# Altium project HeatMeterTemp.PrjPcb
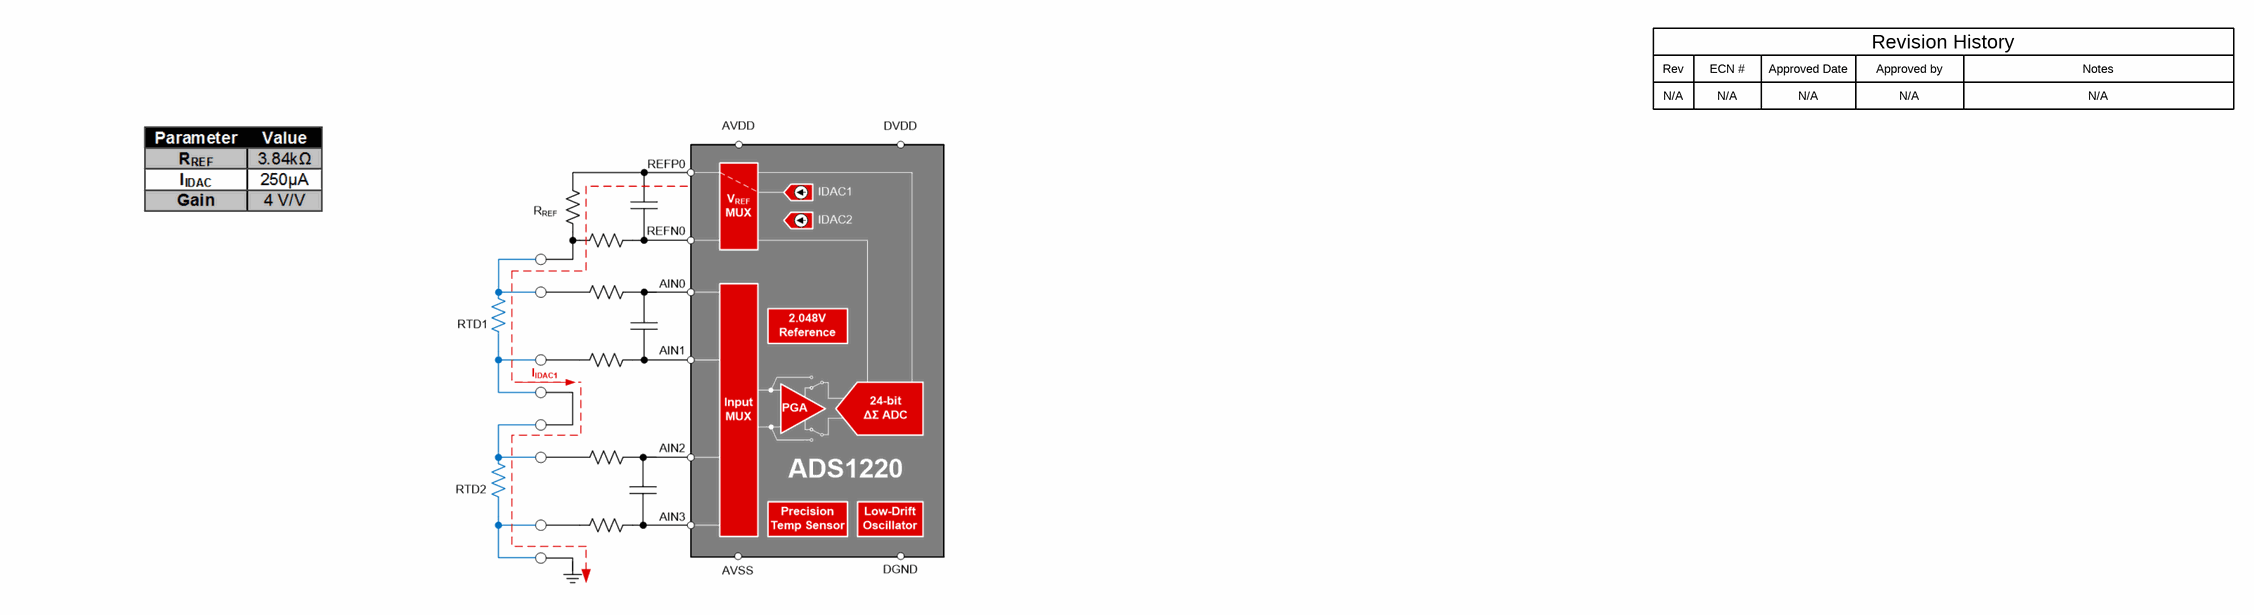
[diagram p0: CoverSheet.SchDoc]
CopyrightYear: 2017; EVM_orderable: shippable; PCB_Layouta0797195: Who did the Layout?; PCB_Rev: E1; PRJ_Customer: Public Release; PRJ_Engineer: MGS; PRJ_Number: TIDA-01526; PRJ_Title: Heat Meter dual 2-/4-wire RTD measurement; SCH_Rev: E1; TechSupport: http://www.ti.com/support; TID: TIDA-01526
3 sheets, 61 parts. Net scope: flat (ports and power ports of the same name join across sheets).
Board file: HeatMeterTemp.PcbDoc
Sheets:
  CoverSheet.SchDoc
  RTD_ADS122U04.SchDoc
  HeatMeterTemp_Hardware.SchDoc

## Sheet CoverSheet.SchDoc
size 431 x 279 mm; Date: Not shown in title block; ApprovedBy: Not shown in title block; CheckedBy: Not shown in title block; Author: Not shown in title block; CompanyName: Not shown in title block; Engineer: Not shown in title block; Organization: Not shown in title block; Address1: Not shown in title block; Address2: Not shown in title block; Address3: Not shown in title block; Address4: Not shown in title block; DocumentNumber: 1; Revision: Use project parameter SCH_Rev; SheetNumber: 1; SheetTotal: 3; PageSetup: Record=PageOptions¦CenterHorizontal=True¦CenterVertical=True¦PrintScale=1.00¦XCorrection=1.00¦YCorrection=1.00¦PrintKind=0¦BorderSize=5000000¦LeftOffset=0¦BottomOffset=0¦Orientation=2¦PaperLength=1000¦PaperWidth=1000¦Scale=100¦PaperSource=15¦PrintQuality=600¦MediaType=1¦DitherType=10¦PaperKind=Letter¦PrintScaleMode=1

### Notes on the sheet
- Rev
- N/A
- ECN #
- Approved Date
- Approved by
- Revision History
- Notes

## Sheet RTD_ADS122U04.SchDoc
size 431 x 279 mm; Date: Not shown in title block; ApprovedBy: Not shown in title block; CheckedBy: Not shown in title block; Author: Not shown in title block; CompanyName: Not shown in title block; Engineer: Not shown in title block; Organization: Not shown in title block; Address1: Not shown in title block; Address2: Not shown in title block; Address3: Not shown in title block; Address4: Not shown in title block; DocumentNumber: 1; Revision: Use project parameter SCH_Rev; SheetNumber: 2; SheetTotal: 3; PageSetup: Record=PageOptions¦CenterHorizontal=True¦CenterVertical=True¦PrintScale=1.00¦XCorrection=1.00¦YCorrection=1.00¦PrintKind=0¦BorderSize=5000000¦LeftOffset=0¦BottomOffset=0¦Orientation=2¦PaperLength=1000¦PaperWidth=1000¦Scale=100¦PaperSource=15¦PrintQuality=600¦MediaType=1¦DitherType=10¦PaperKind=Letter¦PrintScaleMode=1
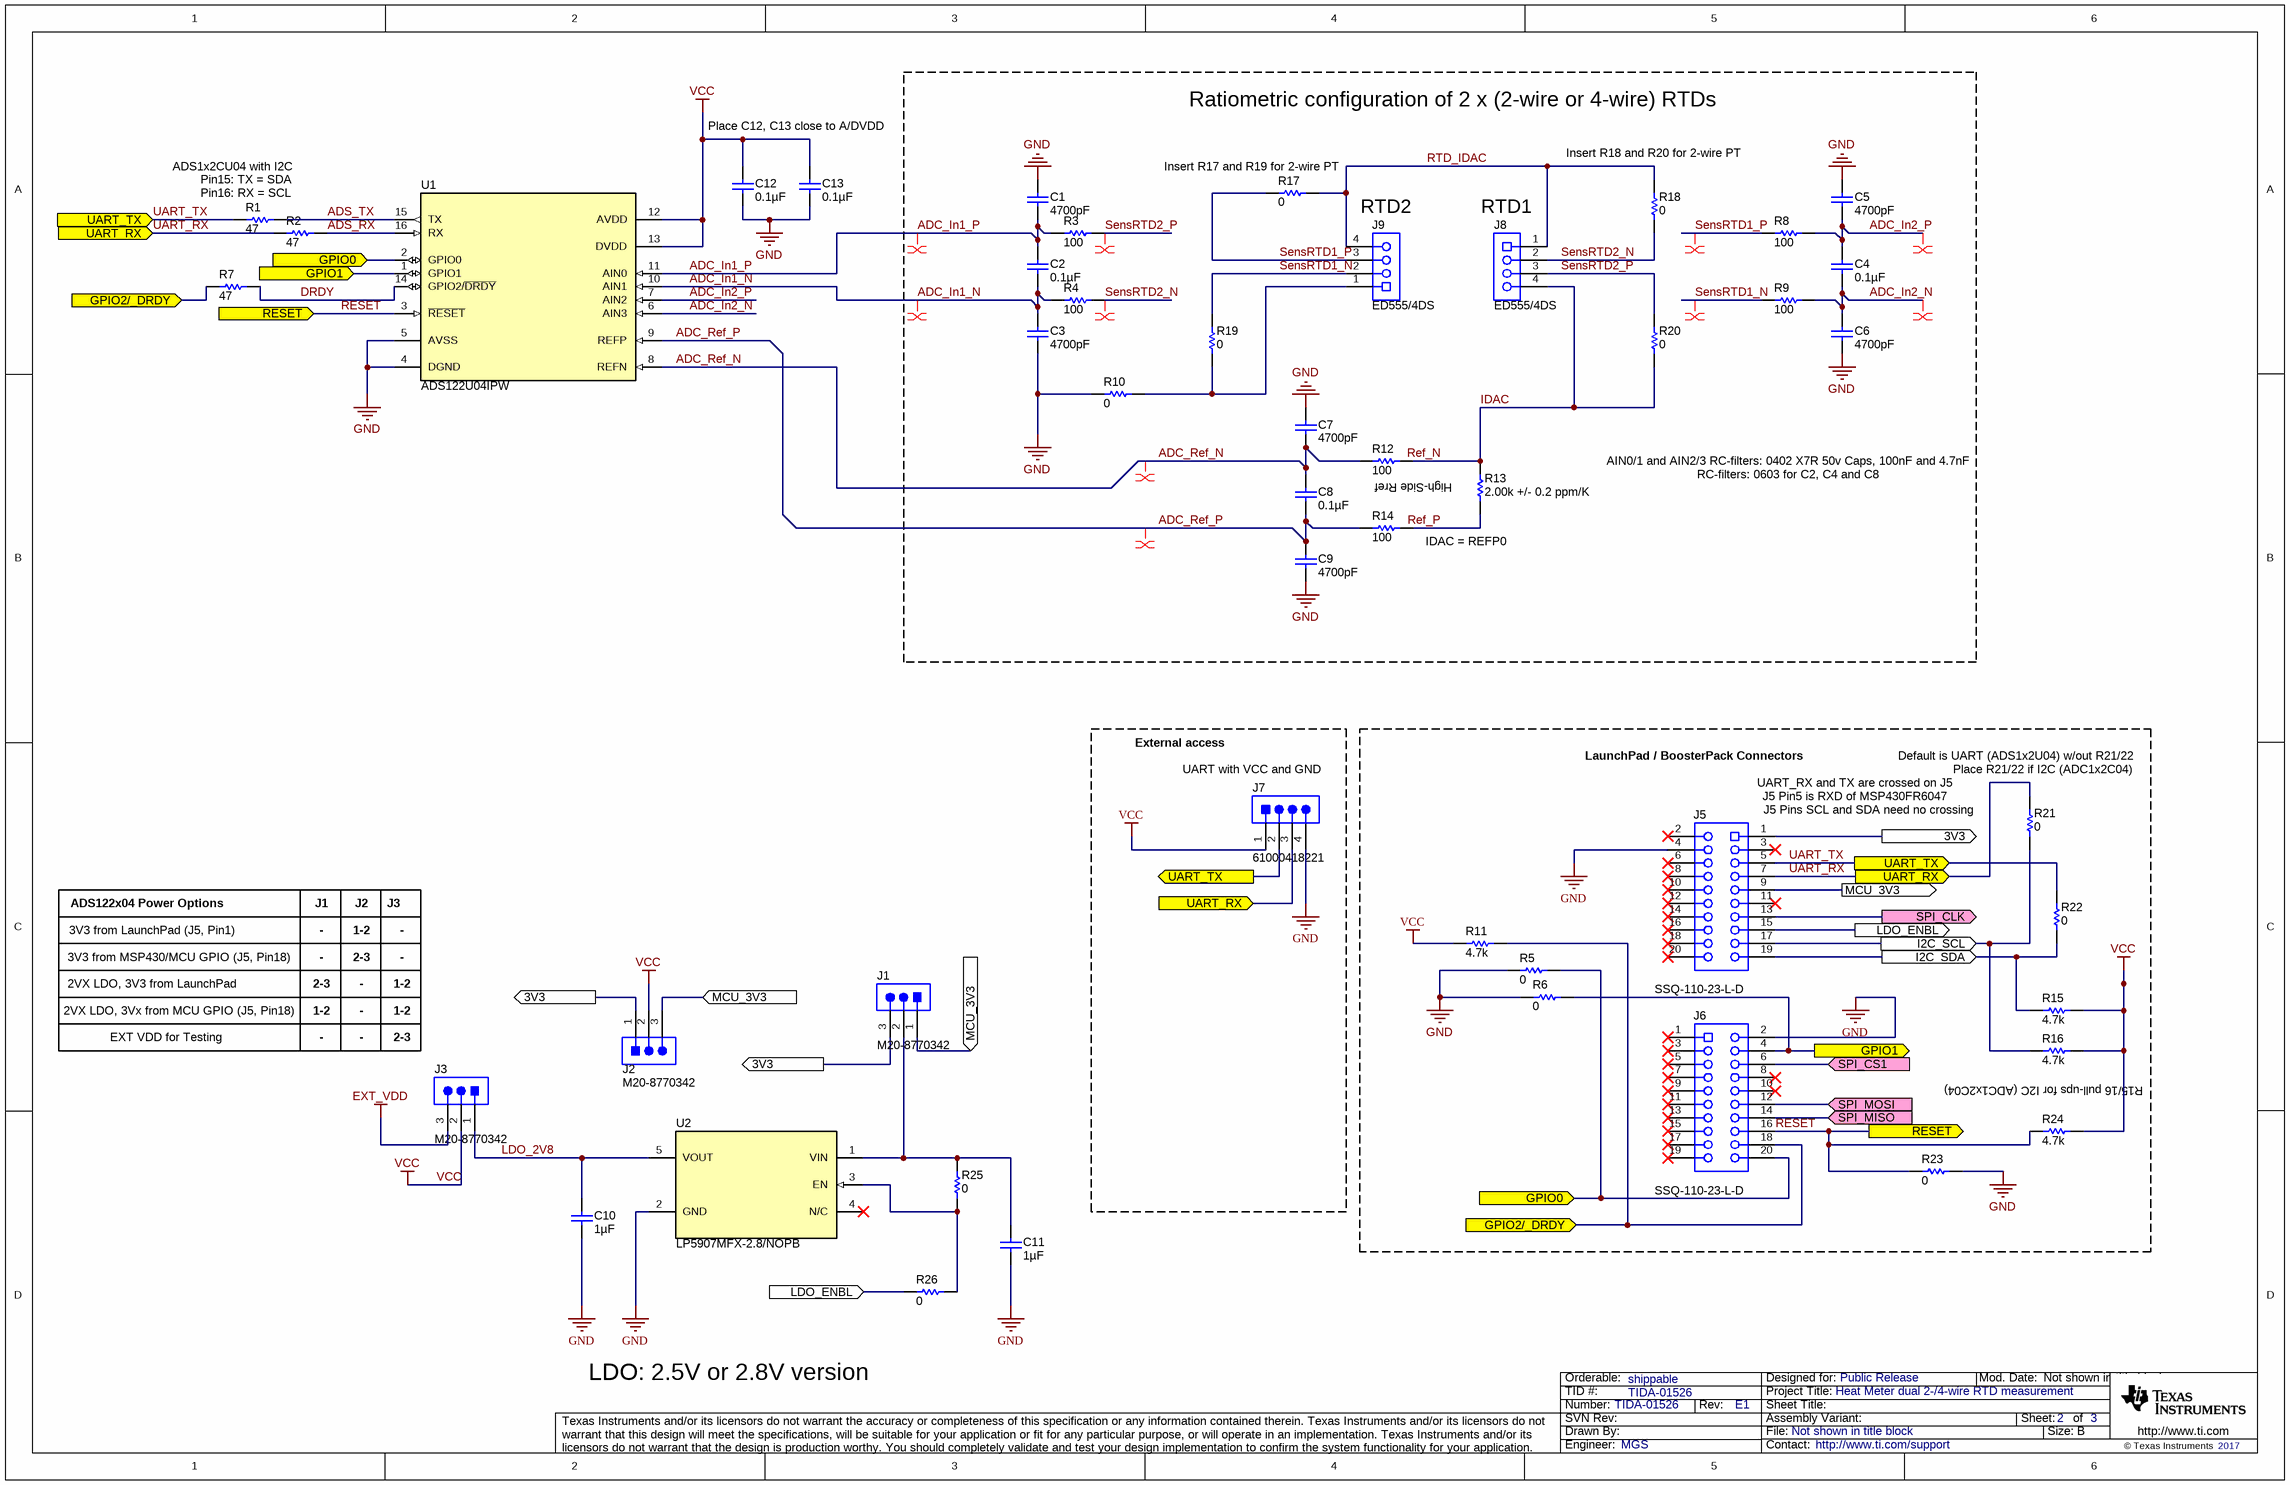
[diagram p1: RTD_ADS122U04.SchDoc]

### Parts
C1  ValueDisplayed: 4700pF  [0402L]  (hidden comment: GCM155R71H472KA37D)
C2  ValueDisplayed: 0.1µF  [0603L]  (hidden comment: GCM188R71H104KA57D)
C3  ValueDisplayed: 4700pF  [0402L]  (hidden comment: GCM155R71H472KA37D)
C4  ValueDisplayed: 0.1µF  [0603L]  (hidden comment: GCM188R71H104KA57D)
C5  ValueDisplayed: 4700pF  [0402L]  (hidden comment: GCM155R71H472KA37D)
C6  ValueDisplayed: 4700pF  [0402L]  (hidden comment: GCM155R71H472KA37D)
C7  ValueDisplayed: 4700pF  [0402L]  (hidden comment: GCM155R71H472KA37D)
C8  ValueDisplayed: 0.1µF  [0603L]  (hidden comment: GCM188R71H104KA57D)
C9  ValueDisplayed: 4700pF  [0402L]  (hidden comment: GCM155R71H472KA37D)
C10  ValueDisplayed: 1µF  [0603L]  (hidden comment: 885012206026)
C11  ValueDisplayed: 1µF  [0603L]  (hidden comment: 885012206026)
C12  ValueDisplayed: 0.1µF  [0402L]  (hidden comment: GRM155R71C104JA88D)
C13  ValueDisplayed: 0.1µF  [0402L]  (hidden comment: GRM155R71C104JA88D)
J1  M20-8770342  [Harwin_M20-87703]
J2  M20-8770342  [Harwin_M20-87703]
J3  M20-8770342  [Harwin_M20-87703]
J5  SSW-110-23-F-D  [CONN_SSW-110-23-F-D]  (value not drawn)
J6  SSW-110-23-F-D  [CONN_SSW-110-23-F-D]  (value not drawn)
J7  61000418221  [Wurth_61000418221]
J8  ED555/4DS  [TERM_BLK_ED555-4DS]
J9  ED555/4DS  [TERM_BLK_ED555-4DS]
R1  ValueDisplayed: 47  [0402L]  (hidden comment: CRCW040247R0JNED)
R2  ValueDisplayed: 47  [0402L]  (hidden comment: CRCW040247R0JNED)
R3  ValueDisplayed: 100  [0402L]  (hidden comment: CRCW0402100RFKED)
R4  ValueDisplayed: 100  [0402L]  (hidden comment: CRCW0402100RFKED)
R5  ValueDisplayed: 0  [0402L]  (hidden comment: CRCW04020000Z0ED)
R6  ValueDisplayed: 0  [0402L]  (hidden comment: CRCW04020000Z0ED)
R7  ValueDisplayed: 47  [0402L]  (hidden comment: CRCW040247R0JNED)
R8  ValueDisplayed: 100  [0402L]  (hidden comment: CRCW0402100RFKED)
R9  ValueDisplayed: 100  [0402L]  (hidden comment: CRCW0402100RFKED)
R10  ValueDisplayed: 0  [0402L]  (hidden comment: CRCW04020000Z0ED)
R11  ValueDisplayed: 4.7k  [0402L]  (hidden comment: CRCW04024K70JNED)
R12  ValueDisplayed: 100  [0402L]  (hidden comment: CRCW0402100RFKED)
R13  ValueDisplayed: 2.00k +/- 0.2 ppm/K  [VSMP_0603]  (hidden comment: Y16362K00000F9R)
R14  ValueDisplayed: 100  [0402L]  (hidden comment: CRCW0402100RFKED)
R15  ValueDisplayed: 4.7k  [0402L]  (hidden comment: CRCW04024K70JNED)
R16  ValueDisplayed: 4.7k  [0402L]  (hidden comment: CRCW04024K70JNED)
R17  ValueDisplayed: 0  [0402L]  (hidden comment: CRCW04020000Z0ED)
R18  ValueDisplayed: 0  [0402L]  (hidden comment: CRCW04020000Z0ED)
R19  ValueDisplayed: 0  [0402L]  (hidden comment: CRCW04020000Z0ED)
R20  ValueDisplayed: 0  [0402L]  (hidden comment: CRCW04020000Z0ED)
R21  ValueDisplayed: 0  [0402L]  (hidden comment: CRCW04020000Z0ED)
R22  ValueDisplayed: 0  [0402L]  (hidden comment: CRCW04020000Z0ED)
R23  ValueDisplayed: 0  [0402L]  (hidden comment: CRCW04020000Z0ED)
R24  ValueDisplayed: 4.7k  [0402L]  (hidden comment: CRCW04024K70JNED)
R25  ValueDisplayed: 0  [0402L]  (hidden comment: CRCW04020000Z0ED)
R26  ValueDisplayed: 0  [0402L]  (hidden comment: CRCW04020000Z0ED)
U1  ADS122U04IPW  [PW0016A_N]
U2  LP5907MFX-2.8/NOPB  [DBV0005A_N]

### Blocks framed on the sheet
Ratiometric configuration of 2 x (2-wire or 4-wire) RTDs: C1-C9 J8 J9 R3 R4 R8-R10 R12-R14 R17-R20

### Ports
3V3, GPIO0, GPIO1, GPIO2/_DRDY, I2C_SCL, I2C_SDA, LDO_ENBL, MCU_3V3, RESET, SPI_CLK, SPI_CS1, SPI_MISO, SPI_MOSI, UART_RX, UART_TX

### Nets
EXT_VDD: J3.3
GND: C1.1 C3.2 C5.1 C6.2 C7.1 C9.2 C10.2 C11.2 C12.1 C13.1 J5.4 J6.2 J7.4 R5.1 R6.1 R10.1 R23.2 U1.4(DGND) U1.5(AVSS) U2.2(GND)
VCC: C12.2 C13.2 J2.2 J3.2 J7.1 R11.1 R15.2 R16.2 R24.2 U1.12(AVDD) U1.13(DVDD)
3V3: J1.3 J2.1 J5.1 ; port 3V3
ADC_In1_N: C2.2 C3.1 R4.1 U1.10(AIN1)
ADC_In1_P: C1.2 C2.1 R3.1 U1.11(AIN0)
ADC_In2_N: C4.2 C6.1 R9.2 U1.6(AIN3)
ADC_In2_P: C4.1 C5.2 R8.2 U1.7(AIN2)
ADC_Ref_N: C7.2 C8.1 R12.1 U1.8(REFN)
ADC_Ref_P: C8.2 C9.1 R14.1 U1.9(REFP)
ADS_RX: R2.2 U1.16(RX)
ADS_TX: R1.2 U1.15(TX)
DRDY: R7.2 U1.14(GPIO2/~{DRDY})
GPIO0: J6.20 R5.2 U1.2(GPIO0) ; port GPIO0
GPIO1: J6.4 R6.2 U1.1(GPIO1) ; port GPIO1
GPIO2/_DRDY: J6.18 R7.1 R11.2 ; port GPIO2/_DRDY
I2C_SCL: J5.17 R16.1 R21.1 ; port I2C_SCL
I2C_SDA: J5.19 R15.1 R22.2 ; port I2C_SDA
IDAC: J8.4 R12.2 R13.2 R20.1
LDO_2V8: C10.1 J3.1 U2.5(VOUT)
LDO_ENBL: J5.15 R26.2 ; port LDO_ENBL
MCU_3V3: J1.1 J2.3 J5.9 ; port MCU_3V3
RESET: J6.16 R23.1 R24.1 U1.3(~{RESET}) ; port RESET
RTD_IDAC: J8.1 J9.4 R17.2 R18.2
SensRTD1_N: J9.2 R9.1 R19.2
SensRTD1_P: J9.3 R8.1 R17.1
SensRTD2_N: J8.2 R4.2 R18.1
SensRTD2_P: J8.3 R3.2 R20.2
SPI_CLK: J5.13 ; port SPI_CLK
SPI_CS1: J6.6 ; port SPI_CS1
SPI_MISO: J6.14 ; port SPI_MISO
SPI_MOSI: J6.12 ; port SPI_MOSI
UART_RX: J5.7 J7.3 R2.1 R21.2 ; port UART_RX
UART_TX: J5.5 J7.2 R1.1 R22.1 ; port UART_TX
NetC11_1: C11.1 J1.2 R25.1 U2.1(VIN)
NetJ9_1: J9.1 R10.2 R19.1
NetR13_1: R13.1 R14.2
NetR25_2: R25.2 R26.1 U2.3(EN)

Not connected (* = marked no-connect by the designer): J5 2* 3* 6* 8* 10* 11* 12* 14* 16* 18* 20*; J6 1* 3* 5* 7* 8* 9* 10* 11* 13* 15* 17* 19*; U2 4(N/C)*

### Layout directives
differential pair: ADC_In1_N, ADC_In1_P, ADC_In2_N, ADC_In2_P, ADC_Ref_N, ADC_Ref_P, SensRTD1_N, SensRTD1_P, SensRTD2_N, SensRTD2_P

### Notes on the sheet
- ADS1x2CU04 with I2C
- Place C12, C13 close to A/DVDD
- (near R17) Insert R17 and R19 for 2-wire PT
- (near R18) Insert R18 and R20 for 2-wire PT
- Pin15: TX = SDA
- Pin16: RX = SCL
- (near J9) RTD2
- (near J8) RTD1
- High-Side Rref
- AIN0/1 and AIN2/3 RC-filters: 0402 X7R 50v Caps, 100nF and 4.7nF
- RC-filters: 0603 for C2, C4 and C8
- IDAC = REFP0
- External access
- (near J7) UART with VCC and GND
- LaunchPad / BoosterPack Connectors
- (near R21) Default is UART (ADS1x2U04) w/out R21/22
- (near R21) Place R21/22 if I2C (ADC1x2C04)
- (near J5) UART_RX and TX are crossed on J5
- (near J5) J5 Pin5 is RXD of MSP430FR6047
- (near J5) J5 Pins SCL and SDA need no crossing
- ADS122x04 Power Options
- J1
- J2
- J3
- 3V3 from LaunchPad (J5, Pin1)
- 3V3 from MSP430/MCU GPIO (J5, Pin18)
- -
- 2-3
- 1-2
- 2VX LDO, 3V3 from LaunchPad
- EXT VDD for Testing
- 2VX LDO, 3Vx from MCU GPIO (J5, Pin18)
- (near J5) SSQ-110-23-L-D
- R15/16 pull-ups for I2C (ADC1x2C04)
- (near J6) SSQ-110-23-L-D
- LDO: 2.5V or 2.8V version
- Labels drawn without touching a wire or pin: Ref_N, Ref_P

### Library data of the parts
C1 C3 C5-C7 C9 = GCM155R71H472KA37D: CAP, CERM, 4700 pF, 50 V,+/- 10%, X7R, AEC-Q200 Grade 1, 0402; Manufacturer: MuRata; Polarized: N; CompType: Capacitor; Value: 4700pF; U/M: EA; Cap_F: 0.0000000047; Tolerance_%: 10; VDC_V: 50; Value2: 50V; TaMin_C: -55; TaMax_C: 125; Cap_Case: 0402; AEC Category: Q200; AEC Qualified: Y; AEC Grade: 1; SizeArea_mm2: 0.5; SizeAreaWB_mm2: 3; SizeZ_mm: 0.6
C2 C4 C8 = GCM188R71H104KA57D: CAP, CERM, 0.1 µF, 50 V,+/- 10%, X7R, 0603; Manufacturer: MuRata; Polarized: N; CompType: Capacitor; Value: 0.1uF; U/M: EA; Cap_F: 0.0000001; Tolerance_%: 10; ESR_ohm: 0.02; Value1: 0.02 ohm; VDC_V: 50; Value2: 50V; IRMS_A: 1.84; TaMin_C: -55; TaMax_C: 125; Cap_Case: 0603; AEC Category: Q200; SizeArea_mm2: 1.28; SizeAreaWB_mm2: 4.68; SizeX_mm: 1.6; SizeY_mm: 0.8; SizeZ_mm: 1; Green_Lifecycle: Active; Green_REACh: Passed
C10 C11 = 885012206026: CAP, CERM, 1 µF, 10 V,+/- 10%, X7R, 0603; Manufacturer: Wurth Elektronik; Polarized: N; CompType: Capacitor; Value: 1uF; U/M: EA; Cap_F: 0.000001; Tolerance_%: 10; Value2: 10V; TaMin_C: -55; TaMax_C: 125; Cap_Case: 0603; SizeArea_mm2: 1.28; SizeAreaWB_mm2: 4.68; SizeX_mm: 1.6; SizeY_mm: 0.8; SizeZ_mm: 1; AEC Category: Q200
C12 C13 = GRM155R71C104JA88D: CAP, CERM, 0.1 µF, 16 V,+/- 5%, X7R, 0402; Manufacturer: MuRata; Polarized: N; CompType: Capacitor; Value: 0.1uF; U/M: EA; Cap_F: 0.0000001; Tolerance_%: 5; VDC_V: 16; Value2: 16V; TaMin_C: -55; TaMax_C: 125; Cap_Case: 0402; AEC Category: Q200; SizeArea_mm2: 0.5; SizeAreaWB_mm2: 3; SizeX_mm: 1; SizeZ_mm: 0.6; Green_Lifecycle: Active; Green_REACh: Passed
J1-J3 = M20-8770342: Header, 2.54mm, 3x1, Gold, SMT; Manufacturer: Harwin; SymbolCreator: a0799628; Pitch_mm: 2.54; Gender: Male; Shrouded: N; Row_Count: 1; Current_A: 3; Cert_UL: Y; Green_Lifecycle: Active; Green_REACh: Passed
J5 J6 = SSW-110-23-F-D: Connector, Receptacle, 100mil, 10x2, Gold plated, TH; Manufacturer: Samtec; SymbolCreator: a0412235; U/M: EA
J7 = 61000418221: Header, 2.54mm, 4x1, Gold, SMT; Manufacturer: Wurth Elektronik; SymbolCreator: a0412235; Pitch_mm: 2.54; Gender: Male; Shrouded: N; Row_Count: 1
J8 J9 = ED555/4DS: Terminal Block, 3.5mm Pitch, 4x1, TH; Manufacturer: On-Shore Technology; SymbolCreator: a0411947; Pitch_mm: 3.5; Gender: Female; Shrouded: N; Row_Count: 1; ContactFinish: Brass; Current_A: 6; Voltage_V: 150; Cert_CULUS: Y; Green_Lifecycle: Not Set; Green_REACh: Incomplete
R1 R2 R7 = CRCW040247R0JNED: RES, 47, 5%, 0.063 W, 0402; Manufacturer: Vishay-Dale; CompType: Resistor; Value: 47; Value_Code: 47R0; Tolerance_%: 5; Power_W: 0.063; Value2: 0.063W; VDC_V: 50; TempCo: 200 ppm/C; EIA_Code: E24; U/M: EA; AEC Category: Q200; SizeArea_mm2: 0.5; SizeX_mm: 1; SizeZ_mm: 0.6; Green_Lifecycle: Active; Green_REACh: Passed
R3 R4 R8 R9 R12 R14 = CRCW0402100RFKED: RES, 100, 1%, 0.063 W, 0402; Manufacturer: Vishay-Dale; CompType: Resistor; Value: 100; Value_Code: 100R; Tolerance_%: 1; Power_W: 0.063; Value2: 0.063W; VDC_V: 50; TempCo: 100 ppm/C; EIA_Code: E96; U/M: EA; AEC Category: Q200
R5 R6 R10 R17-R23 R25 R26 = CRCW04020000Z0ED: RES, 0, 5%, 0.063 W, 0402; Manufacturer: Vishay-Dale; CompType: Resistor; Value: 0; Value_Code: 0000; Tolerance_%: 5; Power_W: 0.063; Value2: 0.063W; VDC_V: 50; TempCo: 200 ppm/C; EIA_Code: E24; U/M: EA; AEC Category: Q200; SizeArea_mm2: 0.5; SizeX_mm: 1; SizeZ_mm: 0.6; Green_Lifecycle: Active; Green_REACh: Passed
R11 R15 R16 R24 = CRCW04024K70JNED: RES, 4.7 k, 5%, 0.063 W, 0402; Manufacturer: Vishay-Dale; CompType: Resistor; Value: 4.7k; Res_ohm: 4700; Value_Code: 4k70; Tolerance_%: 5; Power_W: 0.063; Value2: 0.063W; VDC_V: 50; TempCo: 200 ppm/C; EIA_Code: E24; U/M: EA; AEC Category: Q200; SizeArea_mm2: 0.5; SizeX_mm: 1; SizeZ_mm: 0.6; Green_Lifecycle: Active; Green_REACh: Passed
R13 = Y16362K00000F9R: RES, 2.00 k, 1%, 0.1 W, 0603, +/- 0.2 ppm/K; Manufacturer: Vishay Foil Resistors; CompType: Resistor; Value: 2.00k; Res_ohm: 2000; Value_Code: 2k00; Tolerance_%: 1; Power_W: 0.1; Value2: 0.1W; VDC_V: 20; TempCo: 0.2 ppm/C; EIA_Code: E96; U/M: EA; AEC Category: Q200; AEC Qualified: N
U1 = ADS122U04IPW: 24-Bit, 4-Channel, 2-kSPS, Delta-Sigma ADC with UART Interface, PW0016A (TSSOP-16); Manufacturer: Texas Instruments; SymbolCreator: Altium; SizeArea_mm2: 32; SizeAreaWB_mm2: 58.8; SizeX_mm: 6.4; SizeY_mm: 5; SizeZ_mm: 1.2; CompType: IC; U/M: EA
U2 = CMP-0066015-1: 250-mA Ultra-Low-Noise, Low-IQ LDO, DBV0005A (SOT-23-5); Alternate Manufacturer: Texas Instruments; SizeAreaWB_mm2: 14.82; U/M: EA; SizeZ_mm: 1.45; SizeX_mm: 2.8; SizeY_mm: 2.9; SizeArea_mm2: 8.12; CompType: IC

## Sheet HeatMeterTemp_Hardware.SchDoc
size 431 x 279 mm; Date: Not shown in title block; ApprovedBy: Not shown in title block; CheckedBy: Not shown in title block; Author: Not shown in title block; CompanyName: Not shown in title block; Engineer: Not shown in title block; Organization: Not shown in title block; Address1: Not shown in title block; Address2: Not shown in title block; Address3: Not shown in title block; Address4: Not shown in title block; DocumentNumber: 1; Revision: Use project parameter SCH_Rev; SheetNumber: 3; SheetTotal: 3; PageSetup: Record=PageOptions¦CenterHorizontal=True¦CenterVertical=True¦PrintScale=1.00¦XCorrection=1.00¦YCorrection=1.00¦PrintKind=0¦BorderSize=5000000¦LeftOffset=0¦BottomOffset=0¦Orientation=2¦PaperLength=1000¦PaperWidth=1000¦Scale=100¦PaperSource=15¦PrintQuality=600¦MediaType=1¦DitherType=10¦PaperKind=Letter¦PrintScaleMode=1
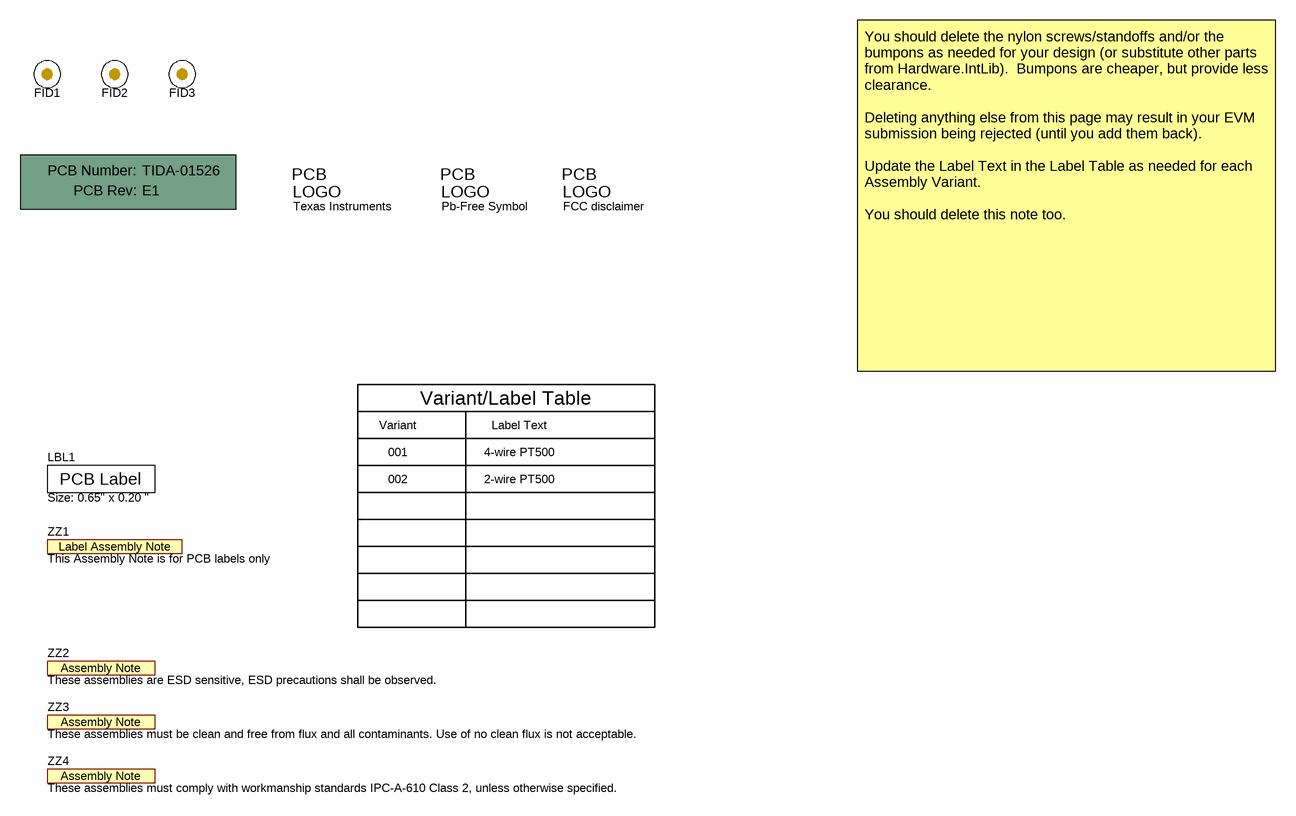
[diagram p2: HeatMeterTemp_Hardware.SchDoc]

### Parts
!PCB1  Printed Circuit Board  (value not drawn)  (mechanical)
FID1  Fiducial  [Fiducial10-20]  (value not drawn)
FID2  Fiducial  [Fiducial10-20]  (value not drawn)
FID3  Fiducial  [Fiducial10-20]  (value not drawn)
LBL1  Size: 0.65" x 0.20 "  [Label_650x200]
Logo1  Texas Instruments  [TI_Symbol_Overlay_Small]  (no BOM)
Logo2  Pb-Free Symbol  [Pb-Free_Overlay_Small]  (no BOM)
Logo3  FCC disclaimer  [FCC_disclaimer]  (no BOM)
ZZ1  This Assembly Note is for PCB labels only  [AssemblyNoteLabel]  (no BOM)
ZZ2  These assemblies are ESD sensitive, ESD precautions shall be observed.  [AssemblyNote]  (no BOM)
ZZ3  These assemblies must be clean and free from flux and all contaminants. Use of no clean flux is not acceptable.  [AssemblyNote]  (no BOM)
ZZ4  These assemblies must comply with workmanship standards IPC-A-610 Class 2, unless otherwise specified.  [AssemblyNote]  (no BOM)

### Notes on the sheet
- Variant
- Variant/Label Table
- Label Text
- You should delete the nylon screws/standoffs and/or the bumpons as needed for your design (or substitute other parts from Hardware.IntLib).  Bumpons are cheaper, but provide less clearance.
  Deleting anything else from this page may result in your EVM submission being rejected (until you add them back).
  Update the Label Text in the Label Table as needed for each Assembly Variant.
  You should delete this note too.
- 001
- 002
- 4-wire PT500
- 2-wire PT500

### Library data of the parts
!PCB1 = PCB: Manufacturer: Any; PartNumber: TIDA-01526; SymbolCreator: a0412235
FID1-FID3 = Fiducial: Fiducial mark.  There is nothing to buy or mount.; SymbolCreator: codlsc
LBL1 = THT-14-423-10: Thermal Transfer Printable Labels, 0.650" W x 0.200" H - 10,000 per roll; Manufacturer: Brady; SymbolCreator: a0412235; CompType: Label
Logo1 = TI_Logo: Texas Instrument Corporate Signature; SymbolCreator: codlsc
Logo2 = Pb-Free: SymbolCreator: a0412235
Logo3 = FCC_disclaimer: SymbolCreator: codlsc
ZZ1 = AssemblyNoteLabel: SymbolCreator: a0412235
ZZ2-ZZ4 = AssemblyNote: SymbolCreator: codlsc

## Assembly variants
001: not fitted FID1 FID2 FID3 R23 R26
2-wire PT500: all parts fitted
